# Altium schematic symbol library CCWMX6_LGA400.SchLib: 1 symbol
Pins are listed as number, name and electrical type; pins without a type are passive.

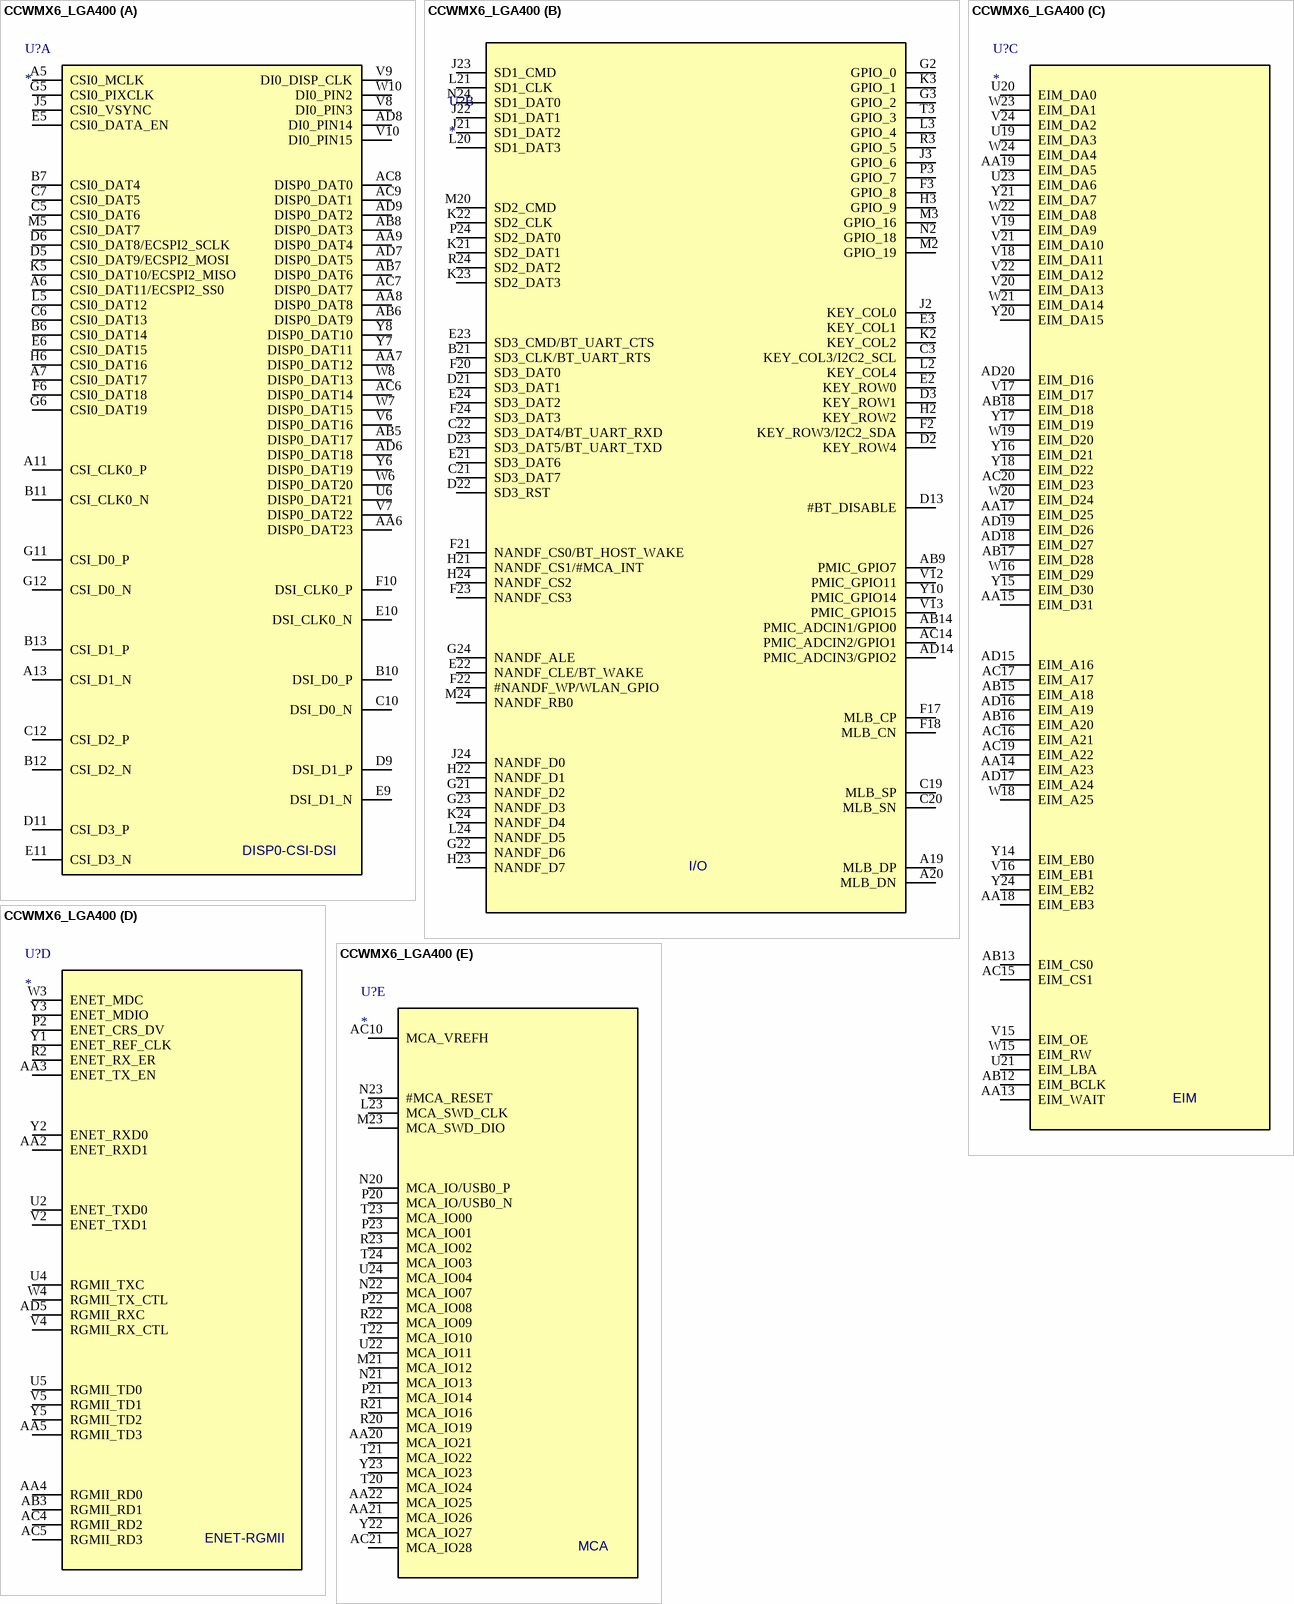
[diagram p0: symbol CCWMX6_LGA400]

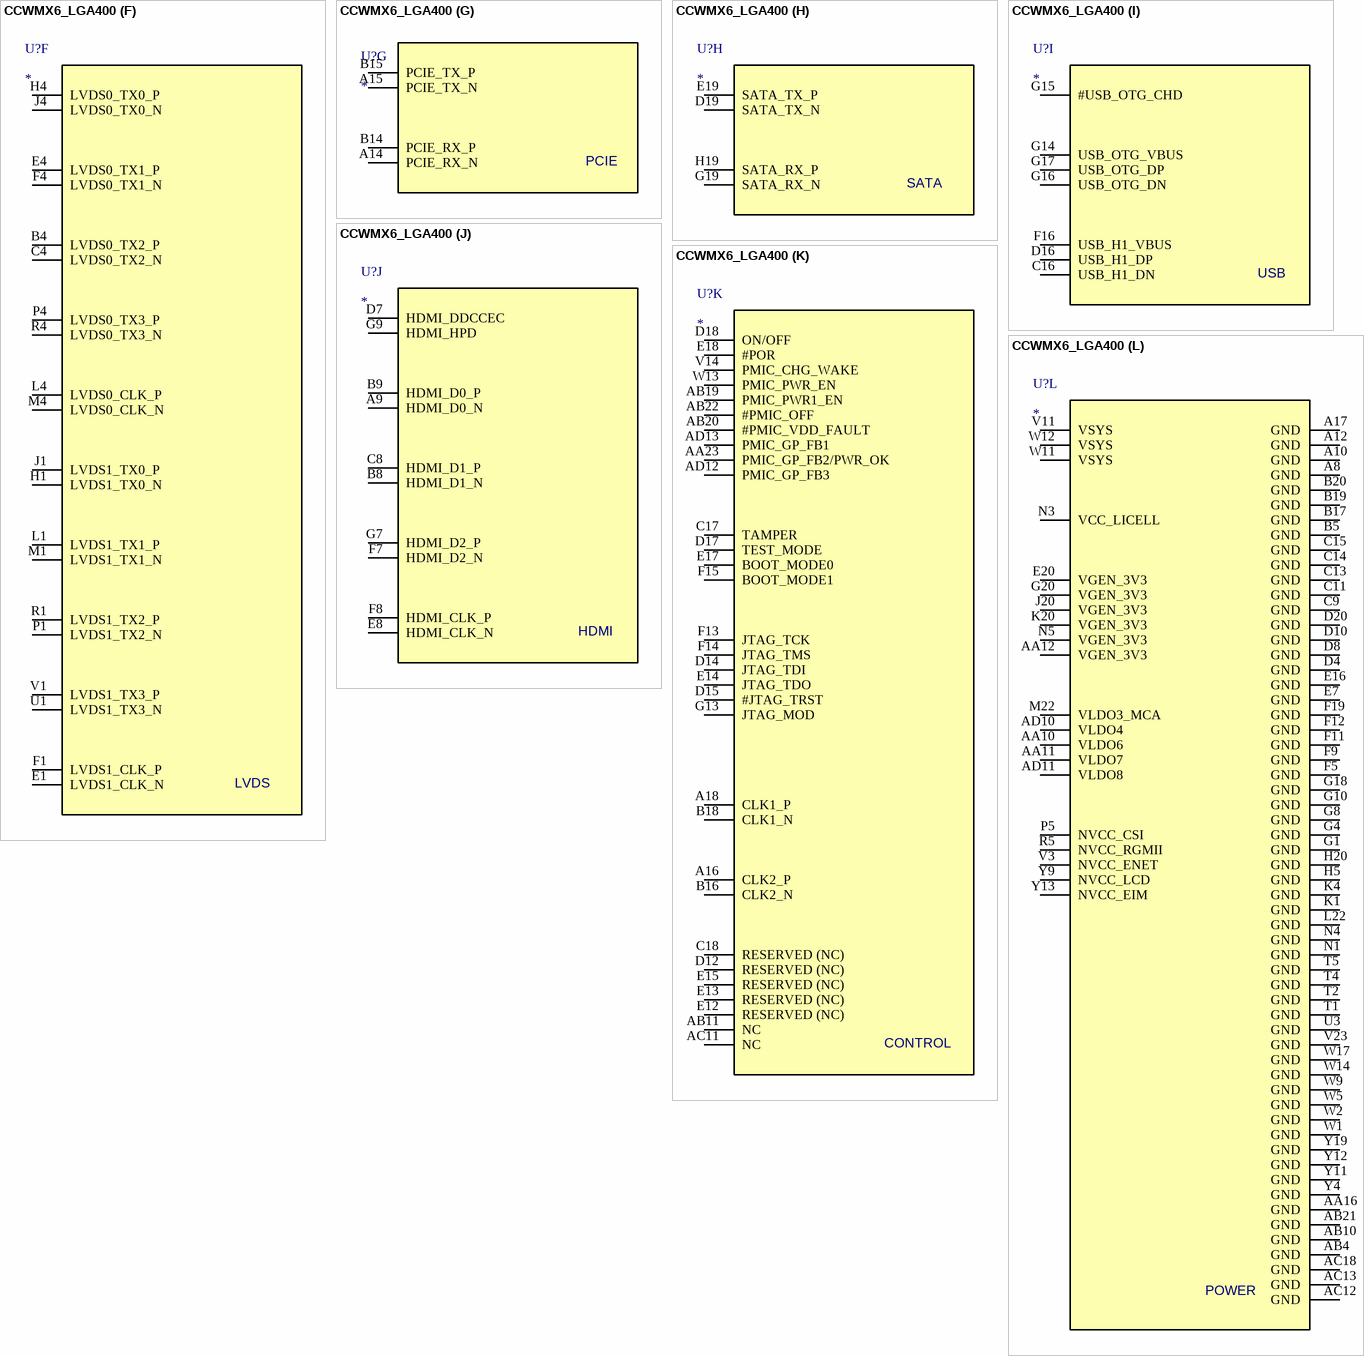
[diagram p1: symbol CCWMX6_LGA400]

## CCWMX6_LGA400
designator U?
part A pins: A5 CSI0_MCLK, A6 CSI0_DAT11/ECSPI2_SS0, A7 CSI0_DAT17, A11 CSI_CLK0_P, A13 CSI_D1_N, AA6 DISP0_DAT23, AA7 DISP0_DAT12, AA8 DISP0_DAT8, AA9 DISP0_DAT4, AB5 DISP0_DAT17, AB6 DISP0_DAT9, AB7 DISP0_DAT6, AB8 DISP0_DAT3, AC6 DISP0_DAT14, AC7 DISP0_DAT7, AC8 DISP0_DAT0, AC9 DISP0_DAT1, AD6 DISP0_DAT18, AD7 DISP0_DAT5, AD8 DI0_PIN14, AD9 DISP0_DAT2, B6 CSI0_DAT14, B7 CSI0_DAT4, B10 DSI_D0_P, B11 CSI_CLK0_N, B12 CSI_D2_N, B13 CSI_D1_P, C5 CSI0_DAT6, C6 CSI0_DAT13, C7 CSI0_DAT5, C10 DSI_D0_N, C12 CSI_D2_P, D5 CSI0_DAT9/ECSPI2_MOSI, D6 CSI0_DAT8/ECSPI2_SCLK, D9 DSI_D1_P, D11 CSI_D3_P, E5 CSI0_DATA_EN, E6 CSI0_DAT15, E9 DSI_D1_N, E10 DSI_CLK0_N, E11 CSI_D3_N, F6 CSI0_DAT18, F10 DSI_CLK0_P, G5 CSI0_PIXCLK, G6 CSI0_DAT19, G11 CSI_D0_P, G12 CSI_D0_N, H6 CSI0_DAT16, J5 CSI0_VSYNC, K5 CSI0_DAT10/ECSPI2_MISO, L5 CSI0_DAT12, M5 CSI0_DAT7, U6 DISP0_DAT21, V6 DISP0_DAT16, V7 DISP0_DAT22, V8 DI0_PIN3, V9 DI0_DISP_CLK, V10 DI0_PIN15, W6 DISP0_DAT20, W7 DISP0_DAT15, W8 DISP0_DAT13, W10 DI0_PIN2, Y6 DISP0_DAT19, Y7 DISP0_DAT11, Y8 DISP0_DAT10
part B pins: A19 MLB_DP, A20 MLB_DN, AB9 PMIC_GPIO7, AB14 PMIC_ADCIN1/GPIO0, AC14 PMIC_ADCIN2/GPIO1, AD14 PMIC_ADCIN3/GPIO2, B21 SD3_CLK/BT_UART_RTS, C3 KEY_COL3/I2C2_SCL, C19 MLB_SP, C20 MLB_SN, C21 SD3_DAT7, C22 SD3_DAT4/BT_UART_RXD, D2 KEY_ROW4, D3 KEY_ROW1, D13 #BT_DISABLE, D21 SD3_DAT1, D22 SD3_RST, D23 SD3_DAT5/BT_UART_TXD, E2 KEY_ROW0, E3 KEY_COL1, E21 SD3_DAT6, E22 NANDF_CLE/BT_WAKE, E23 SD3_CMD/BT_UART_CTS, E24 SD3_DAT2, F2 KEY_ROW3/I2C2_SDA, F3 GPIO_8, F17 MLB_CP, F18 MLB_CN, F20 SD3_DAT0, F21 NANDF_CS0/BT_HOST_WAKE, F22 #NANDF_WP/WLAN_GPIO, F23 NANDF_CS3, F24 SD3_DAT3, G2 GPIO_0, G3 GPIO_2, G21 NANDF_D2, G22 NANDF_D6, G23 NANDF_D3, G24 NANDF_ALE, H2 KEY_ROW2, H3 GPIO_9, H21 NANDF_CS1/#MCA_INT, H22 NANDF_D1, H23 NANDF_D7, H24 NANDF_CS2, J2 KEY_COL0, J3 GPIO_6, J21 SD1_DAT2, J22 SD1_DAT1, J23 SD1_CMD, J24 NANDF_D0, K2 KEY_COL2, K3 GPIO_1, K21 SD2_DAT1, K22 SD2_CLK, K23 SD2_DAT3, K24 NANDF_D4, L2 KEY_COL4, L3 GPIO_4, L20 SD1_DAT3, L21 SD1_CLK, L24 NANDF_D5, M2 GPIO_19, M3 GPIO_16, M20 SD2_CMD, M24 NANDF_RB0, N2 GPIO_18, N24 SD1_DAT0, P3 GPIO_7, P24 SD2_DAT0, R3 GPIO_5, R24 SD2_DAT2, T3 GPIO_3, V12 PMIC_GPIO11, V13 PMIC_GPIO15, Y10 PMIC_GPIO14
part C pins: AA13 EIM_WAIT, AA14 EIM_A23, AA15 EIM_D31, AA17 EIM_D25, AA18 EIM_EB3, AA19 EIM_DA5, AB12 EIM_BCLK, AB13 EIM_CS0, AB15 EIM_A18, AB16 EIM_A20, AB17 EIM_D28, AB18 EIM_D18, AC15 EIM_CS1, AC16 EIM_A21, AC17 EIM_A17, AC19 EIM_A22, AC20 EIM_D23, AD15 EIM_A16, AD16 EIM_A19, AD17 EIM_A24, AD18 EIM_D27, AD19 EIM_D26, AD20 EIM_D16, U19 EIM_DA3, U20 EIM_DA0, U21 EIM_LBA, U23 EIM_DA6, V15 EIM_OE, V16 EIM_EB1, V17 EIM_D17, V18 EIM_DA11, V19 EIM_DA9, V20 EIM_DA13, V21 EIM_DA10, V22 EIM_DA12, V24 EIM_DA2, W15 EIM_RW, W16 EIM_D29, W18 EIM_A25, W19 EIM_D20, W20 EIM_D24, W21 EIM_DA14, W22 EIM_DA8, W23 EIM_DA1, W24 EIM_DA4, Y14 EIM_EB0, Y15 EIM_D30, Y16 EIM_D21, Y17 EIM_D19, Y18 EIM_D22, Y20 EIM_DA15, Y21 EIM_DA7, Y24 EIM_EB2
part D pins: AA2 ENET_RXD1, AA3 ENET_TX_EN, AA4 RGMII_RD0, AA5 RGMII_TD3, AB3 RGMII_RD1, AC4 RGMII_RD2, AC5 RGMII_RD3, AD5 RGMII_RXC, P2 ENET_CRS_DV, R2 ENET_RX_ER, U2 ENET_TXD0, U4 RGMII_TXC, U5 RGMII_TD0, V2 ENET_TXD1, V4 RGMII_RX_CTL, V5 RGMII_TD1, W3 ENET_MDC, W4 RGMII_TX_CTL, Y1 ENET_REF_CLK, Y2 ENET_RXD0, Y3 ENET_MDIO, Y5 RGMII_TD2
part E pins: AA20 MCA_IO21, AA21 MCA_IO26, AA22 MCA_IO25, AC10 MCA_VREFH, AC21 MCA_IO28, L23 MCA_SWD_CLK, M21 MCA_IO12, M23 MCA_SWD_DIO, N20 MCA_IO/USB0_P, N21 MCA_IO13, N22 MCA_IO07, N23 #MCA_RESET, P20 MCA_IO/USB0_N, P21 MCA_IO14, P22 MCA_IO08, P23 MCA_IO01, R20 MCA_IO19, R21 MCA_IO16, R22 MCA_IO09, R23 MCA_IO02, T20 MCA_IO24, T21 MCA_IO22, T22 MCA_IO10, T23 MCA_IO00, T24 MCA_IO03, U22 MCA_IO11, U24 MCA_IO04, Y22 MCA_IO27, Y23 MCA_IO23
part F pins: B4 LVDS0_TX2_P, C4 LVDS0_TX2_N, E1 LVDS1_CLK_N, E4 LVDS0_TX1_P, F1 LVDS1_CLK_P, F4 LVDS0_TX1_N, H1 LVDS1_TX0_N, H4 LVDS0_TX0_P, J1 LVDS1_TX0_P, J4 LVDS0_TX0_N, L1 LVDS1_TX1_P, L4 LVDS0_CLK_P, M1 LVDS1_TX1_N, M4 LVDS0_CLK_N, P1 LVDS1_TX2_N, P4 LVDS0_TX3_P, R1 LVDS1_TX2_P, R4 LVDS0_TX3_N, U1 LVDS1_TX3_N, V1 LVDS1_TX3_P
part G pins: A14 PCIE_RX_N, A15 PCIE_TX_N, B14 PCIE_RX_P, B15 PCIE_TX_P
part H pins: D19 SATA_TX_N, E19 SATA_TX_P, G19 SATA_RX_N, H19 SATA_RX_P
part I pins: C16 USB_H1_DN, D16 USB_H1_DP, F16 USB_H1_VBUS, G14 USB_OTG_VBUS, G15 #USB_OTG_CHD, G16 USB_OTG_DN, G17 USB_OTG_DP
part J pins: A9 HDMI_D0_N, B8 HDMI_D1_N, B9 HDMI_D0_P, C8 HDMI_D1_P, D7 HDMI_DDCCEC, E8 HDMI_CLK_N, F7 HDMI_D2_N, F8 HDMI_CLK_P, G7 HDMI_D2_P, G9 HDMI_HPD
part K pins: A16 CLK2_P, A18 CLK1_P, AA23 PMIC_GP_FB2/PWR_OK, AB11 NC, AB19 PMIC_PWR1_EN, AB20 #PMIC_VDD_FAULT, AB22 #PMIC_OFF, AC11 NC, AD12 PMIC_GP_FB3, AD13 PMIC_GP_FB1, B16 CLK2_N, B18 CLK1_N, C17 TAMPER, C18 RESERVED (NC), D12 RESERVED (NC), D14 JTAG_TDI, D15 #JTAG_TRST, D17 TEST_MODE, D18 ON/OFF, E12 RESERVED (NC), E13 RESERVED (NC), E14 JTAG_TDO, E15 RESERVED (NC), E17 BOOT_MODE0, E18 #POR, F13 JTAG_TCK, F14 JTAG_TMS, F15 BOOT_MODE1, G13 JTAG_MOD, V14 PMIC_CHG_WAKE, W13 PMIC_PWR_EN
part L pins: A8 GND, A10 GND, A12 GND, A17 GND, AA10 VLDO6, AA11 VLDO7, AA12 VGEN_3V3, AA16 GND, AB4 GND, AB10 GND, AB21 GND, AC12 GND, AC13 GND, AC18 GND, AD10 VLDO4, AD11 VLDO8, B5 GND, B17 GND, B19 GND, B20 GND, C9 GND, C11 GND, C13 GND, C14 GND, C15 GND, D4 GND, D8 GND, D10 GND, D20 GND, E7 GND, E16 GND, E20 VGEN_3V3, F5 GND, F9 GND, F11 GND, F12 GND, F19 GND, G1 GND, G4 GND, G8 GND, G10 GND, G18 GND, G20 VGEN_3V3, H5 GND, H20 GND, J20 VGEN_3V3, K1 GND, K4 GND, K20 VGEN_3V3, L22 GND, M22 VLDO3_MCA, N1 GND, N3 VCC_LICELL, N4 GND, N5 VGEN_3V3, P5 NVCC_CSI, R5 NVCC_RGMII, T1 GND, T2 GND, T4 GND, T5 GND, U3 GND, V3 NVCC_ENET, V11 VSYS, V23 GND, W1 GND, W2 GND, W5 GND, W9 GND, W11 VSYS, W12 VSYS, W14 GND, W17 GND, Y4 GND, Y9 NVCC_LCD, Y11 GND, Y12 GND, Y13 NVCC_EIM, Y19 GND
